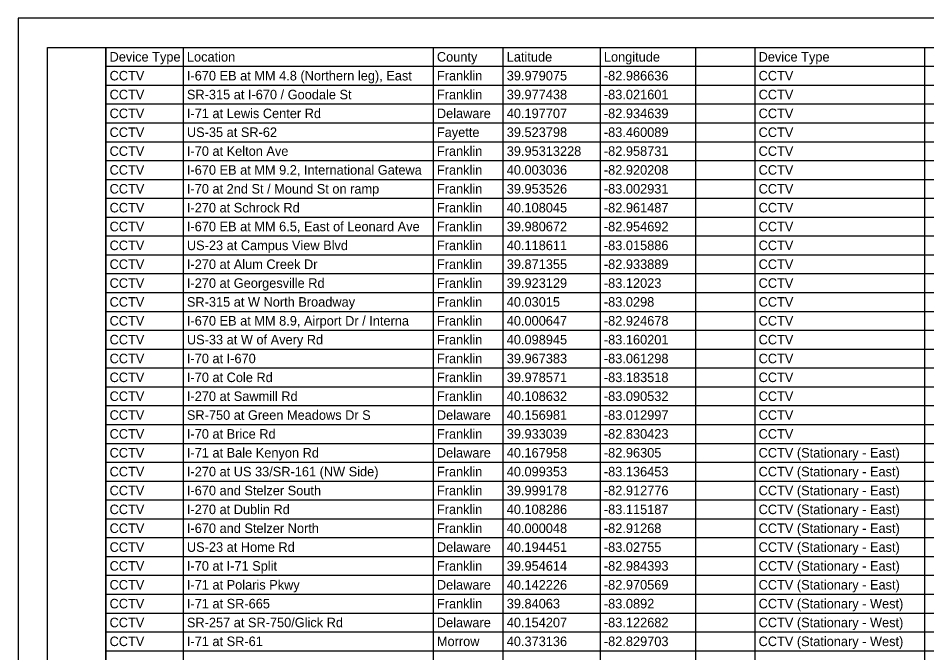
# Model space of a CAD drawing. Extents: x 0 to 34, y 0 to 22.
# Drawn here: x 0 to 15.56, y 11.13 to 22 of the extents above; entities that cross this region are included whole.
import ezdxf

# ---------------------------------------------------------------- set-up
doc = ezdxf.new("R2010")
doc.units = 0
for name, color, linetype in [('SH_Border', 7, 'Continuous'), ('SH_Cut_Line', 7, 'Continuous'), ('SH_Text', 7, 'Continuous')]:
    doc.layers.add(name, color=color, linetype=linetype)

msp = doc.modelspace()

# ---------------------------------------------------------------- linework, layer by layer
at = {"layer": 'SH_Border'}
for points in [[(0.5, 21.5), (1.5, 21.5), (1.5, 0.5), (0.5, 0.5)], [(1.5, 21.5), (33.5, 21.5), (33.5, 0.5), (1.5, 0.5)]]:
    msp.add_lwpolyline(points, close=True, dxfattribs=at)
at = {"layer": 'SH_Cut_Line'}
msp.add_lwpolyline([(0, 0), (34, 0), (34, 22), (0, 22)], close=True, dxfattribs=at)
at = {"layer": 'SH_Text'}
for p, q in [((1.5, 21.5), (24.888, 21.5)), ((1.5, 21.5), (1.5, 0.502)), ((2.824, 21.5), (2.824, 0.502)), ((7.105, 21.5), (7.105, 0.502)), ((8.3, 21.5), (8.3, 0.502)), ((9.964, 21.5), (9.964, 0.502)), ((11.595, 21.5), (11.595, 0.502)), ((12.613, 21.5), (12.613, 0.502)), ((15.52, 21.5), (15.52, 0.502)), ((1.5, 21.177), (24.888, 21.177)), ((1.5, 20.854), (24.888, 20.854)), ((1.5, 20.531), (24.888, 20.531)), ((1.5, 20.208), (24.888, 20.208)), ((1.5, 19.884), (24.888, 19.884)), ((1.5, 19.561), (24.888, 19.561)), ((1.5, 19.238), (24.888, 19.238)), ((1.5, 18.915), (24.888, 18.915)), ((1.5, 18.592), (24.888, 18.592)), ((1.5, 18.269), (24.888, 18.269)), ((1.5, 17.946), (24.888, 17.946)), ((1.5, 17.623), (24.888, 17.623)), ((1.5, 17.3), (24.888, 17.3)), ((1.5, 16.977), (24.888, 16.977)), ((1.5, 16.654), (24.888, 16.654)), ((1.5, 16.331), (24.888, 16.331)), ((1.5, 16.008), (24.888, 16.008)), ((1.5, 15.685), (24.888, 15.685)), ((1.5, 15.362), (24.888, 15.362)), ((1.5, 15.039), (24.888, 15.039)), ((1.5, 14.716), (24.888, 14.716)), ((1.5, 14.393), (24.888, 14.393)), ((1.5, 14.07), (24.888, 14.07)), ((1.5, 13.747), (24.888, 13.747)), ((1.5, 13.424), (24.888, 13.424)), ((1.5, 13.101), (24.888, 13.101)), ((1.5, 12.778), (24.888, 12.778)), ((1.5, 12.455), (24.888, 12.455)), ((1.5, 12.131), (24.888, 12.131)), ((1.5, 11.808), (24.888, 11.808)), ((1.5, 11.485), (24.888, 11.485)), ((1.5, 11.162), (24.888, 11.162))]:
    msp.add_line(p, q, dxfattribs=at)

# ---------------------------------------------------------------- texts
for s, height, p in [('Device Type', 0.16346, (1.565, 21.256)), ('Location', 0.1635, (2.889, 21.256)), ('County', 0.1635, (7.169, 21.256)), ('Latitude', 0.1635, (8.365, 21.256)), ('Longitude', 0.1635, (10.028, 21.256)), ('Device Type', 0.16346, (12.677, 21.256)), ('CCTV', 0.1635, (1.565, 20.933)), ('I-670 EB at MM 4.8 (Northern leg), East', 0.16346, (2.889, 20.933)), ('Franklin', 0.1635, (7.169, 20.933)), ('39.979075', 0.1635, (8.365, 20.933)), ('-82.986636', 0.1635, (10.028, 20.933)), ('CCTV', 0.1635, (12.677, 20.933)), ('CCTV', 0.1635, (1.565, 20.61)), ('SR-315 at I-670 / Goodale St', 0.16346, (2.889, 20.61)), ('Franklin', 0.1635, (7.169, 20.61)), ('39.977438', 0.1635, (8.365, 20.61)), ('-83.021601', 0.1635, (10.028, 20.61)), ('CCTV', 0.1635, (12.677, 20.61)), ('CCTV', 0.1635, (1.565, 20.287)), ('I-71 at Lewis Center Rd', 0.16346, (2.889, 20.287)), ('Delaware', 0.1635, (7.169, 20.287)), ('40.197707', 0.1635, (8.365, 20.287)), ('-82.934639', 0.1635, (10.028, 20.287)), ('CCTV', 0.1635, (12.677, 20.287)), ('CCTV', 0.1635, (1.565, 19.964)), ('US-35 at SR-62', 0.16346, (2.889, 19.964)), ('Fayette', 0.1635, (7.169, 19.964)), ('39.523798', 0.1635, (8.365, 19.964)), ('-83.460089', 0.1635, (10.028, 19.964)), ('CCTV', 0.1635, (12.677, 19.964)), ('CCTV', 0.1635, (1.565, 19.641)), ('I-70 at Kelton Ave', 0.16346, (2.889, 19.641)), ('Franklin', 0.1635, (7.169, 19.641)), ('39.95313228', 0.16346, (8.365, 19.641)), ('-82.958731', 0.1635, (10.028, 19.641)), ('CCTV', 0.1635, (12.677, 19.641)), ('CCTV', 0.1635, (1.565, 19.318)), ('I-670 EB at MM 9.2, International Gatewa', 0.16346, (2.889, 19.318)), ('Franklin', 0.1635, (7.169, 19.318)), ('40.003036', 0.1635, (8.365, 19.318)), ('-82.920208', 0.1635, (10.028, 19.318)), ('CCTV', 0.1635, (12.677, 19.318)), ('CCTV', 0.1635, (1.565, 18.995)), ('I-70 at 2nd St / Mound St on ramp', 0.16346, (2.889, 18.995)), ('Franklin', 0.1635, (7.169, 18.995)), ('39.953526', 0.1635, (8.365, 18.995)), ('-83.002931', 0.1635, (10.028, 18.995)), ('CCTV', 0.1635, (12.677, 18.995)), ('CCTV', 0.1635, (1.565, 18.672)), ('I-270 at Schrock Rd', 0.16346, (2.889, 18.672)), ('Franklin', 0.1635, (7.169, 18.672)), ('40.108045', 0.1635, (8.365, 18.672)), ('-82.961487', 0.1635, (10.028, 18.672)), ('CCTV', 0.1635, (12.677, 18.672)), ('CCTV', 0.1635, (1.565, 18.349)), ('I-670 EB at MM 6.5, East of Leonard Ave', 0.16346, (2.889, 18.349)), ('Franklin', 0.1635, (7.169, 18.349)), ('39.980672', 0.1635, (8.365, 18.349)), ('-82.954692', 0.1635, (10.028, 18.349)), ('CCTV', 0.1635, (12.677, 18.349)), ('CCTV', 0.1635, (1.565, 18.026)), ('US-23 at Campus View Blvd', 0.16346, (2.889, 18.026)), ('Franklin', 0.1635, (7.169, 18.026)), ('40.118611', 0.1635, (8.365, 18.026)), ('-83.015886', 0.1635, (10.028, 18.026)), ('CCTV', 0.1635, (12.677, 18.026)), ('CCTV', 0.1635, (1.565, 17.703)), ('I-270 at Alum Creek Dr', 0.16346, (2.889, 17.703)), ('Franklin', 0.1635, (7.169, 17.703)), ('39.871355', 0.1635, (8.365, 17.703)), ('-82.933889', 0.1635, (10.028, 17.703)), ('CCTV', 0.1635, (12.677, 17.703)), ('CCTV', 0.1635, (1.565, 17.38)), ('I-270 at Georgesville Rd', 0.16346, (2.889, 17.38)), ('Franklin', 0.1635, (7.169, 17.38)), ('39.923129', 0.1635, (8.365, 17.38)), ('-83.12023', 0.1635, (10.028, 17.38)), ('CCTV', 0.1635, (12.677, 17.38)), ('CCTV', 0.1635, (1.565, 17.057)), ('SR-315 at W North Broadway', 0.16346, (2.889, 17.057)), ('Franklin', 0.1635, (7.169, 17.057)), ('40.03015', 0.1635, (8.365, 17.057)), ('-83.0298', 0.1635, (10.028, 17.057)), ('CCTV', 0.1635, (12.677, 17.057)), ('CCTV', 0.1635, (1.565, 16.734)), ('I-670 EB at MM 8.9, Airport Dr / Interna', 0.16346, (2.889, 16.734)), ('Franklin', 0.1635, (7.169, 16.734)), ('40.000647', 0.1635, (8.365, 16.734)), ('-82.924678', 0.1635, (10.028, 16.734)), ('CCTV', 0.1635, (12.677, 16.734)), ('CCTV', 0.1635, (1.565, 16.411)), ('US-33 at W of Avery Rd', 0.16346, (2.889, 16.411)), ('Franklin', 0.1635, (7.169, 16.411)), ('40.098945', 0.1635, (8.365, 16.411)), ('-83.160201', 0.1635, (10.028, 16.411)), ('CCTV', 0.1635, (12.677, 16.411)), ('CCTV', 0.1635, (1.565, 16.088)), ('I-70 at I-670', 0.16346, (2.889, 16.088)), ('Franklin', 0.1635, (7.169, 16.088)), ('39.967383', 0.1635, (8.365, 16.088)), ('-83.061298', 0.1635, (10.028, 16.088)), ('CCTV', 0.1635, (12.677, 16.088)), ('CCTV', 0.1635, (1.565, 15.765)), ('I-70 at Cole Rd', 0.16346, (2.889, 15.765)), ('Franklin', 0.1635, (7.169, 15.765)), ('39.978571', 0.1635, (8.365, 15.765)), ('-83.183518', 0.1635, (10.028, 15.765)), ('CCTV', 0.1635, (12.677, 15.765)), ('CCTV', 0.1635, (1.565, 15.442)), ('I-270 at Sawmill Rd', 0.16346, (2.889, 15.442)), ('Franklin', 0.1635, (7.169, 15.442)), ('40.108632', 0.1635, (8.365, 15.442)), ('-83.090532', 0.1635, (10.028, 15.442)), ('CCTV', 0.1635, (12.677, 15.442)), ('CCTV', 0.1635, (1.565, 15.119)), ('SR-750 at Green Meadows Dr S', 0.16346, (2.889, 15.119)), ('Delaware', 0.1635, (7.169, 15.119)), ('40.156981', 0.1635, (8.365, 15.119)), ('-83.012997', 0.1635, (10.028, 15.119)), ('CCTV', 0.1635, (12.677, 15.119)), ('CCTV', 0.1635, (1.565, 14.796)), ('I-70 at Brice Rd', 0.16346, (2.889, 14.796)), ('Franklin', 0.1635, (7.169, 14.796)), ('39.933039', 0.1635, (8.365, 14.796)), ('-82.830423', 0.1635, (10.028, 14.796)), ('CCTV', 0.1635, (12.677, 14.796)), ('CCTV', 0.1635, (1.565, 14.473)), ('I-71 at Bale Kenyon Rd', 0.16346, (2.889, 14.473)), ('Delaware', 0.1635, (7.169, 14.473)), ('40.167958', 0.1635, (8.365, 14.473)), ('-82.96305', 0.1635, (10.028, 14.473)), ('CCTV (Stationary - East)', 0.16346, (12.677, 14.473)), ('CCTV', 0.1635, (1.565, 14.15)), ('I-270 at US 33/SR-161 (NW Side)', 0.16346, (2.889, 14.15)), ('Franklin', 0.1635, (7.169, 14.15)), ('40.099353', 0.1635, (8.365, 14.15)), ('-83.136453', 0.1635, (10.028, 14.15)), ('CCTV (Stationary - East)', 0.16346, (12.677, 14.15)), ('CCTV', 0.1635, (1.565, 13.826)), ('I-670 and Stelzer South', 0.16346, (2.889, 13.826)), ('Franklin', 0.1635, (7.169, 13.826)), ('39.999178', 0.1635, (8.365, 13.826)), ('-82.912776', 0.1635, (10.028, 13.826)), ('CCTV (Stationary - East)', 0.16346, (12.677, 13.826)), ('CCTV', 0.1635, (1.565, 13.503)), ('I-270 at Dublin Rd', 0.16346, (2.889, 13.503)), ('Franklin', 0.1635, (7.169, 13.503)), ('40.108286', 0.1635, (8.365, 13.503)), ('-83.115187', 0.1635, (10.028, 13.503)), ('CCTV (Stationary - East)', 0.16346, (12.677, 13.503)), ('CCTV', 0.1635, (1.565, 13.18)), ('I-670 and Stelzer North', 0.16346, (2.889, 13.18)), ('Franklin', 0.1635, (7.169, 13.18)), ('40.000048', 0.1635, (8.365, 13.18)), ('-82.91268', 0.1635, (10.028, 13.18)), ('CCTV (Stationary - East)', 0.16346, (12.677, 13.18)), ('CCTV', 0.1635, (1.565, 12.857)), ('US-23 at Home Rd', 0.16346, (2.889, 12.857)), ('Delaware', 0.1635, (7.169, 12.857)), ('40.194451', 0.1635, (8.365, 12.857)), ('-83.02755', 0.1635, (10.028, 12.857)), ('CCTV (Stationary - East)', 0.16346, (12.677, 12.857)), ('CCTV', 0.1635, (1.565, 12.534)), ('I-70 at I-71 Split', 0.16346, (2.889, 12.534)), ('Franklin', 0.1635, (7.169, 12.534)), ('39.954614', 0.1635, (8.365, 12.534)), ('-82.984393', 0.1635, (10.028, 12.534)), ('CCTV (Stationary - East)', 0.16346, (12.677, 12.534)), ('CCTV', 0.1635, (1.565, 12.211)), ('I-71 at Polaris Pkwy', 0.16346, (2.889, 12.211)), ('Delaware', 0.1635, (7.169, 12.211)), ('40.142226', 0.1635, (8.365, 12.211)), ('-82.970569', 0.1635, (10.028, 12.211)), ('CCTV (Stationary - East)', 0.16346, (12.677, 12.211)), ('CCTV', 0.1635, (1.565, 11.888)), ('I-71 at SR-665', 0.16346, (2.889, 11.888)), ('Franklin', 0.1635, (7.169, 11.888)), ('39.84063', 0.1635, (8.365, 11.888)), ('-83.0892', 0.1635, (10.028, 11.888)), ('CCTV (Stationary - West)', 0.16346, (12.677, 11.888)), ('CCTV', 0.1635, (1.565, 11.565)), ('SR-257 at SR-750/Glick Rd', 0.16346, (2.889, 11.565)), ('Delaware', 0.1635, (7.169, 11.565)), ('40.154207', 0.1635, (8.365, 11.565)), ('-83.122682', 0.1635, (10.028, 11.565)), ('CCTV (Stationary - West)', 0.16346, (12.677, 11.565)), ('CCTV', 0.1635, (1.565, 11.242)), ('I-71 at SR-61', 0.16346, (2.889, 11.242)), ('Morrow', 0.1635, (7.169, 11.242)), ('40.373136', 0.1635, (8.365, 11.242)), ('-82.829703', 0.1635, (10.028, 11.242)), ('CCTV (Stationary - West)', 0.16346, (12.677, 11.242))]:
    msp.add_text(s, height=height, dxfattribs=at).set_placement(p)

doc.saveas('drawing.dxf')
